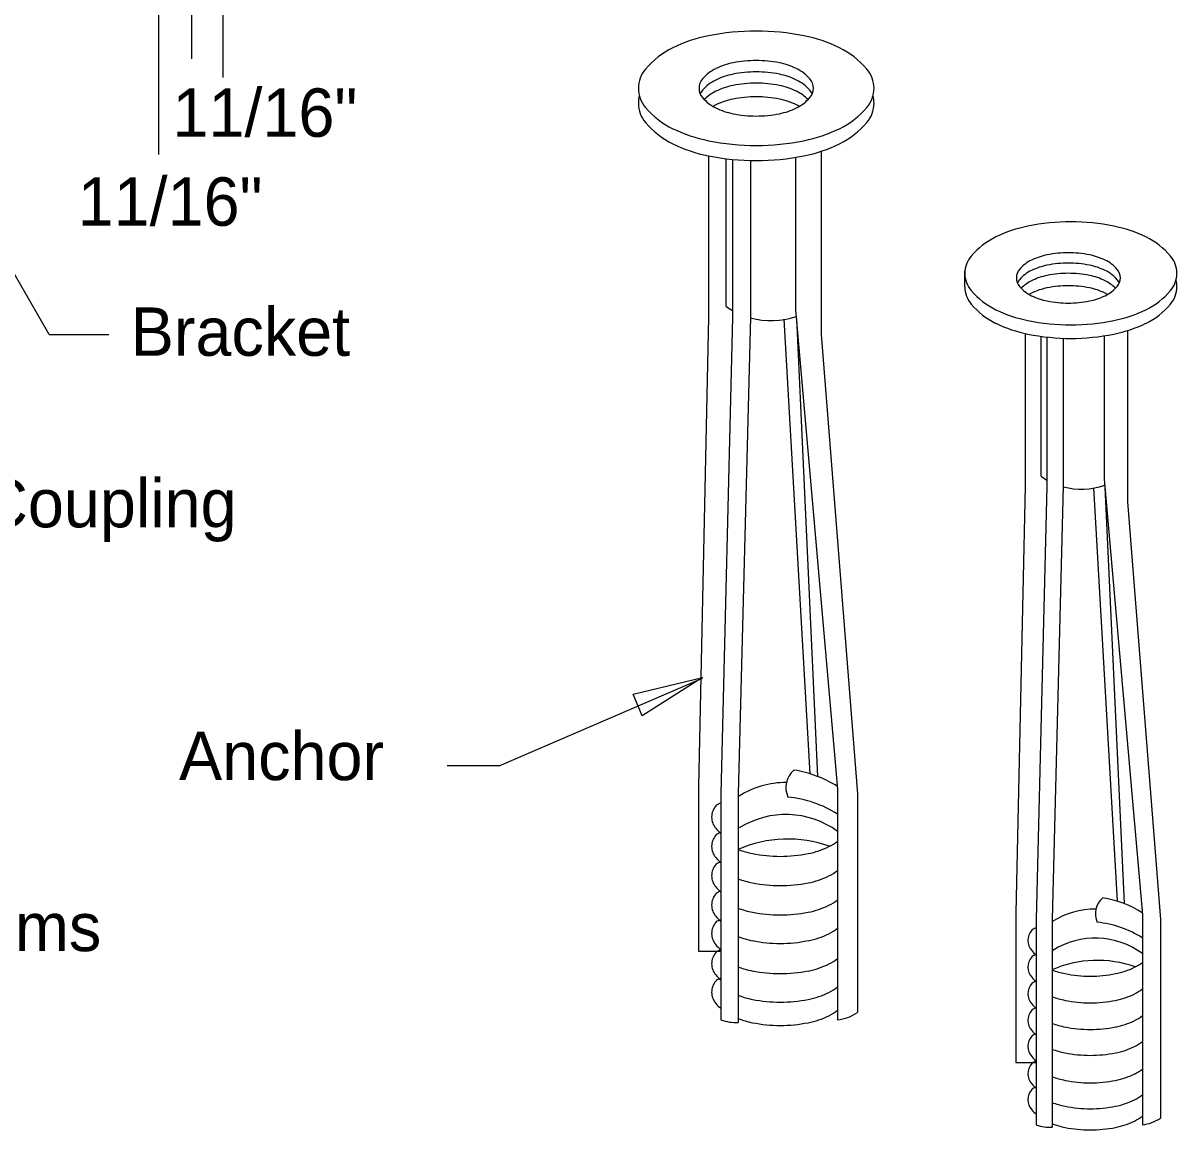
# Model space of a CAD drawing. Extents: x 12.3 to 19.6, y 5.9 to 16.2.
# Drawn here: x 17.486 to 18.916, y 8.1 to 9.472 of the extents above; entities that cross this region are included whole.
import ezdxf

# ---------------------------------------------------------------- set-up
doc = ezdxf.new("R2010")
doc.units = 0
for name, color, linetype in [('DETL-DIMS', 7, 'Continuous'), ('DETL-LINE', 7, 'Continuous'), ('DETL-NOTE', 7, 'Continuous')]:
    doc.layers.add(name, color=color, linetype=linetype)

msp = doc.modelspace()

# ---------------------------------------------------------------- linework, layer by layer
at = {"layer": 'DETL-DIMS'}
for p, q in [((17.6945, 10.224), (17.6945, 9.4278)), ((17.6539, 9.5709), (17.6539, 9.3091)), ((17.7336, 9.5458), (17.7336, 9.4046)), ((17.5181, 9.086), (17.3812, 9.3241)), ((17.5181, 9.086), (17.5922, 9.086)), ((18.076, 8.551), (18.3282, 8.6596)), ((18.076, 8.551), (18.0115, 8.551))]:
    msp.add_line(p, q, dxfattribs=at)
at = {"layer": 'DETL-LINE'}
for p, q in [((18.4753, 9.3132), (18.4753, 9.0858)), ((18.3356, 9.3075), (18.3356, 9.1074)), ((18.3576, 9.1207), (18.3576, 9.304)), ((18.3656, 9.3031), (18.3656, 9.1074)), ((18.3878, 9.3017), (18.3878, 9.1074)), ((18.4437, 9.3057), (18.4437, 9.1166)), ((18.6535, 9.145), (18.6536, 9.1644)), ((18.4437, 9.1166), (18.4957, 8.5223)), ((18.3356, 9.1074), (18.3232, 8.5254)), ((18.3656, 9.1074), (18.3509, 8.5162)), ((18.3878, 9.1074), (18.3725, 8.5162)), ((18.4292, 9.1051), (18.4612, 8.5412)), ((18.4446, 9.1058), (18.4708, 8.5379)), ((18.4753, 9.0858), (18.5204, 8.5162)), ((18.7281, 9.0872), (18.7281, 8.898)), ((18.8263, 9.0843), (18.8263, 8.9064)), ((18.8551, 9.0908), (18.8551, 8.8784)), ((18.748, 8.9101), (18.748, 9.0837)), ((18.7553, 9.0828), (18.7553, 8.898)), ((18.7755, 9.0813), (18.7755, 8.898)), ((18.8263, 8.9064), (18.8736, 8.3661)), ((18.7281, 8.898), (18.7167, 8.3689)), ((18.7553, 8.898), (18.742, 8.3605)), ((18.7755, 8.898), (18.7616, 8.3605)), ((18.8131, 8.8959), (18.8422, 8.3832)), ((18.8271, 8.8965), (18.8509, 8.3803)), ((18.8551, 8.8784), (18.896, 8.3605)), ((18.3232, 8.5254), (18.3232, 8.321)), ((18.3509, 8.5162), (18.3509, 8.236)), ((18.3725, 8.5162), (18.3725, 8.2329)), ((18.4957, 8.5223), (18.4957, 8.236)), ((18.5204, 8.5162), (18.5204, 8.2452)), ((18.7167, 8.3689), (18.7167, 8.1831)), ((18.742, 8.3605), (18.742, 8.1058)), ((18.7616, 8.3605), (18.7616, 8.103)), ((18.8736, 8.3661), (18.8736, 8.1058)), ((18.896, 8.3605), (18.896, 8.1142)), ((18.3232, 8.321), (18.3509, 8.321)), ((18.7167, 8.1831), (18.742, 8.1831))]:
    msp.add_line(p, q, dxfattribs=at)
msp.add_lwpolyline([(18.2535, 8.6132), (18.2421, 8.64), (18.3282, 8.6606)], close=True, dxfattribs=at)
for centre, radius, start, end in [((18.3719, 9.2758), 0.1842, 101.3709, 115.8973), ((18.3948, 9.1622), 0.3, 90, 101.3709), ((18.3948, 9.1622), 0.3, 78.6291, 90), ((18.4176, 9.2758), 0.1842, 64.1027, 78.6291), ((18.3373, 9.3471), 0.1049, 115.8973, 139.5312), ((18.4522, 9.3471), 0.1049, 40.4688, 64.1027), ((18.2855, 9.3913), 0.0368, 139.5312, 180), ((18.3669, 9.3698), 0.0509, 115.8664, 139.4922), ((18.3837, 9.3351), 0.0895, 101.3557, 115.8664), ((18.3948, 9.2799), 0.1458, 90, 101.3557), ((18.3948, 9.2799), 0.1458, 78.6443, 90), ((18.4059, 9.3351), 0.0895, 64.1336, 78.6443), ((18.4227, 9.3698), 0.0509, 40.5078, 64.1336), ((18.5041, 9.3913), 0.0368, 0, 40.4688), ((18.3417, 9.3913), 0.0178, 139.4922, 180), ((18.3669, 9.3557), 0.0509, 115.8664, 139.4922), ((18.3837, 9.321), 0.0895, 101.3557, 115.8664), ((18.3948, 9.2658), 0.1458, 90, 101.3557), ((18.3948, 9.2658), 0.1458, 78.6443, 90), ((18.4059, 9.321), 0.0895, 64.1336, 78.6443), ((18.4227, 9.3557), 0.0509, 40.5078, 64.1336), ((18.4479, 9.3913), 0.0178, 360, 40.5078), ((18.2855, 9.3913), 0.0368, 180, 220.4688), ((18.3417, 9.3913), 0.0178, 180, 220.5078), ((18.3417, 9.3772), 0.0178, 139.4922, 156.7461), ((18.3669, 9.3417), 0.0509, 115.8664, 135.6907), ((18.3837, 9.307), 0.0895, 101.3557, 115.8664), ((18.3948, 9.2518), 0.1458, 90, 101.3557), ((18.3948, 9.2518), 0.1458, 78.6443, 90), ((18.4059, 9.307), 0.0895, 64.1336, 78.6443), ((18.4227, 9.3417), 0.0509, 44.3093, 64.1336), ((18.4479, 9.3913), 0.0178, 319.4922, 360), ((18.4479, 9.3772), 0.0178, 23.2539, 40.5078), ((18.5041, 9.3913), 0.0368, 319.5312, 360), ((18.2855, 9.3726), 0.0368, 165.2366, 180), ((18.2855, 9.3726), 0.0368, 180, 220.4688), ((18.3669, 9.4128), 0.0509, 220.5078, 244.1336), ((18.3669, 9.3248), 0.0509, 115.8664, 120.2074), ((18.3837, 9.2901), 0.0895, 101.3557, 115.8664), ((18.3948, 9.2349), 0.1458, 90, 101.3557), ((18.3948, 9.2349), 0.1458, 78.6443, 90), ((18.4059, 9.2901), 0.0895, 64.1336, 78.6443), ((18.4227, 9.4128), 0.0509, 295.8664, 319.4922), ((18.4227, 9.3248), 0.0509, 59.7926, 64.1336), ((18.5041, 9.3726), 0.0368, 319.5312, 360), ((18.5041, 9.3726), 0.0368, 0, 14.7634), ((18.3373, 9.4355), 0.1049, 220.4688, 244.1027), ((18.3837, 9.4475), 0.0895, 244.1336, 258.6443), ((18.3948, 9.5027), 0.1458, 258.6443, 270), ((18.3948, 9.5027), 0.1458, 270, 281.3557), ((18.4059, 9.4475), 0.0895, 281.3557, 295.8664), ((18.4522, 9.4355), 0.1049, 295.8973, 319.5312), ((18.3373, 9.4168), 0.1049, 220.4688, 244.1027), ((18.4522, 9.4168), 0.1049, 295.8973, 319.5312), ((18.3719, 9.5069), 0.1842, 244.1027, 258.6291), ((18.4176, 9.5069), 0.1842, 281.3709, 295.8973), ((18.3719, 9.4881), 0.1842, 244.1027, 258.6291), ((18.3948, 9.6204), 0.3, 258.6291, 270), ((18.3948, 9.6204), 0.3, 270, 281.3709), ((18.4176, 9.4881), 0.1842, 281.3709, 295.8973), ((18.3948, 9.6016), 0.3, 258.6291, 270), ((18.3948, 9.6016), 0.3, 270, 281.3709), ((18.7644, 9.0578), 0.1658, 101.3709, 115.8973), ((18.785, 8.9557), 0.27, 90, 101.3709), ((18.785, 8.9557), 0.27, 78.6291, 90), ((18.8055, 9.0578), 0.1658, 64.1027, 78.6291), ((18.7333, 9.122), 0.0944, 115.8973, 139.5312), ((18.8367, 9.122), 0.0944, 40.4688, 64.1027), ((18.7717, 9.105), 0.0813, 101.3557, 115.8664), ((18.7818, 9.0548), 0.1325, 90, 101.3557), ((18.7818, 9.0548), 0.1325, 78.6443, 90), ((18.7919, 9.105), 0.0813, 64.1336, 78.6443), ((18.6866, 9.1618), 0.0331, 139.5312, 180), ((18.7564, 9.1366), 0.0463, 115.8664, 139.4922), ((18.7717, 9.0922), 0.0813, 101.3557, 115.8664), ((18.7818, 9.042), 0.1325, 90, 101.3557), ((18.7818, 9.042), 0.1325, 78.6443, 90), ((18.7919, 9.0922), 0.0813, 64.1336, 78.6443), ((18.8072, 9.1366), 0.0463, 40.5078, 64.1336), ((18.8833, 9.1618), 0.0331, 360, 40.4688), ((18.6866, 9.1618), 0.0331, 180, 220.4688), ((18.7336, 9.1561), 0.0162, 139.4922, 180), ((18.7336, 9.1561), 0.0162, 180, 220.5078), ((18.7564, 9.1238), 0.0463, 115.8664, 139.4922), ((18.7717, 9.0795), 0.0813, 101.3557, 115.8664), ((18.7818, 9.0293), 0.1325, 90, 101.3557), ((18.7818, 9.0293), 0.1325, 78.6443, 90), ((18.7919, 9.0795), 0.0813, 64.1336, 78.6443), ((18.8072, 9.1238), 0.0463, 40.5078, 64.1336), ((18.8301, 9.1561), 0.0162, 360, 40.5078), ((18.8301, 9.1561), 0.0162, 319.4922, 0), ((18.8833, 9.1618), 0.0331, 319.5312, 360), ((18.6866, 9.145), 0.0331, 180, 220.4688), ((18.7336, 9.1433), 0.0162, 139.4922, 156.7461), ((18.7564, 9.1756), 0.0463, 220.5078, 244.1336), ((18.7564, 9.111), 0.0463, 115.8664, 135.6907), ((18.7717, 9.0641), 0.0813, 101.3557, 115.8664), ((18.7818, 9.0139), 0.1325, 90, 101.3557), ((18.7818, 9.0139), 0.1325, 78.6443, 90), ((18.7919, 9.0641), 0.0813, 64.1336, 78.6443), ((18.8072, 9.111), 0.0463, 44.3093, 64.1336), ((18.8072, 9.1756), 0.0463, 295.8664, 319.4922), ((18.8301, 9.1433), 0.0162, 23.2539, 40.5078), ((18.8833, 9.145), 0.0331, 319.5312, 0), ((18.8833, 9.145), 0.0331, 360, 14.7634), ((18.7333, 9.2016), 0.0944, 220.4688, 244.1027), ((18.7564, 9.0957), 0.0463, 115.8664, 120.2074), ((18.7717, 9.2072), 0.0813, 244.1336, 258.6443), ((18.7818, 9.2574), 0.1325, 258.6443, 270), ((18.7818, 9.2574), 0.1325, 270, 281.3557), ((18.7919, 9.2072), 0.0813, 281.3557, 295.8664), ((18.8072, 9.0957), 0.0463, 59.7926, 64.1336), ((18.8367, 9.2016), 0.0944, 295.8973, 319.5312), ((18.4128, 9.1985), 0.0954, 234.6116, 240.3143), ((18.7333, 9.1847), 0.0944, 220.4688, 244.1027), ((18.7644, 9.2658), 0.1658, 244.1027, 258.6291), ((18.8055, 9.2658), 0.1658, 281.3709, 295.8973), ((18.8367, 9.1847), 0.0944, 295.8973, 319.5312), ((18.4128, 9.1985), 0.0954, 254.7883, 289.3036), ((18.7644, 9.249), 0.1658, 244.1027, 258.6291), ((18.785, 9.368), 0.27, 258.6291, 270), ((18.785, 9.368), 0.27, 270, 281.3709), ((18.8055, 9.249), 0.1658, 281.3709, 295.8973), ((18.785, 9.3511), 0.27, 258.6291, 270), ((18.785, 9.3511), 0.27, 270, 281.3709), ((18.7982, 8.9808), 0.0867, 234.6116, 240.3143), ((18.7982, 8.9808), 0.0867, 254.7883, 289.3036), ((18.4597, 8.5241), 0.0281, 129.9978, 204.8964), ((18.4203, 8.4062), 0.1411, 57.6772, 81.3099), ((18.4316, 8.4219), 0.1084, 89.658, 122.2181), ((18.4203, 8.3719), 0.1411, 57.6772, 84.3464), ((18.361, 8.4875), 0.0214, 139.4922, 180), ((18.3912, 8.4617), 0.0611, 138.7828, 139.4922), ((18.3607, 8.4769), 0.0295, 109.4731, 121.692), ((18.361, 8.4875), 0.0214, 180, 220.5078), ((18.4316, 8.3823), 0.1084, 53.7599, 122.2181), ((18.3912, 8.5133), 0.0611, 220.5078, 228.7285), ((18.361, 8.4511), 0.0214, 139.4922, 180), ((18.3912, 8.4253), 0.0611, 138.7828, 139.4922), ((18.3607, 8.4405), 0.0295, 109.4731, 121.692), ((18.4341, 8.307), 0.1533, 70.2819, 113.692), ((18.4582, 8.5058), 0.0611, 295.8664, 307.9171), ((18.361, 8.4511), 0.0214, 180, 220.5078), ((18.4114, 8.5475), 0.1074, 248.7495, 258.6443), ((18.4247, 8.6137), 0.1749, 258.6443, 270), ((18.4247, 8.6137), 0.1749, 270, 281.3557), ((18.438, 8.5475), 0.1074, 281.3557, 295.8664), ((18.361, 8.4148), 0.0214, 139.4922, 180), ((18.3912, 8.4769), 0.0611, 220.5078, 228.7285), ((18.3912, 8.389), 0.0611, 138.7828, 139.4922), ((18.3607, 8.4041), 0.0295, 109.4731, 121.692), ((18.361, 8.4148), 0.0214, 180, 220.5078), ((18.438, 8.5111), 0.1074, 281.3557, 295.8664), ((18.4582, 8.4695), 0.0611, 295.8664, 307.9171), ((18.3912, 8.4406), 0.0611, 220.5078, 228.7285), ((18.4114, 8.5111), 0.1074, 248.7495, 258.6443), ((18.4247, 8.5774), 0.1749, 258.6443, 270), ((18.4247, 8.5774), 0.1749, 270, 281.3557), ((18.361, 8.3784), 0.0214, 139.4922, 180), ((18.3912, 8.3526), 0.0611, 138.7828, 139.4922), ((18.3607, 8.3678), 0.0295, 109.4731, 121.692), ((18.4582, 8.4331), 0.0611, 295.8664, 307.9171), ((18.8408, 8.3677), 0.0255, 129.9978, 204.8964), ((18.805, 8.2605), 0.1282, 57.6772, 81.3099), ((18.361, 8.3784), 0.0214, 180, 220.5078), ((18.4114, 8.4747), 0.1074, 248.7495, 258.6443), ((18.4247, 8.541), 0.1749, 258.6443, 270), ((18.4247, 8.541), 0.1749, 270, 281.3557), ((18.438, 8.4747), 0.1074, 281.3557, 295.8664), ((18.8153, 8.2748), 0.0986, 89.658, 122.2181), ((18.361, 8.3431), 0.0214, 139.4922, 180), ((18.3912, 8.4042), 0.0611, 220.5078, 228.7285), ((18.3912, 8.3173), 0.0611, 138.7828, 139.4922), ((18.3607, 8.3324), 0.0295, 109.4731, 121.692), ((18.805, 8.2294), 0.1282, 57.6772, 84.3464), ((18.361, 8.3431), 0.0214, 180, 220.5078), ((18.438, 8.4394), 0.1074, 281.3557, 295.8664), ((18.4582, 8.3978), 0.0611, 295.8664, 307.9171), ((18.7511, 8.3345), 0.0194, 139.4922, 180), ((18.7786, 8.311), 0.0555, 138.7828, 139.4922), ((18.7509, 8.3248), 0.0268, 109.4731, 121.692), ((18.3912, 8.3689), 0.0611, 220.5078, 228.7285), ((18.4114, 8.4394), 0.1074, 248.7495, 258.6443), ((18.4247, 8.5057), 0.1749, 258.6443, 270), ((18.4247, 8.5057), 0.1749, 270, 281.3557), ((18.7511, 8.3345), 0.0194, 180, 220.5078), ((18.8153, 8.2388), 0.0986, 53.7599, 122.2181), ((18.361, 8.3056), 0.0214, 139.4922, 180), ((18.3912, 8.2798), 0.0611, 138.7828, 139.4922), ((18.3607, 8.295), 0.0295, 109.4731, 121.692), ((18.4582, 8.3603), 0.0611, 295.8664, 307.9171), ((18.7511, 8.3014), 0.0194, 139.4922, 180), ((18.7786, 8.3579), 0.0555, 220.5078, 228.7285), ((18.7786, 8.278), 0.0555, 138.7828, 139.4922), ((18.7509, 8.2918), 0.0268, 109.4731, 121.692), ((18.361, 8.3056), 0.0214, 180, 220.5078), ((18.4114, 8.4019), 0.1074, 248.7495, 258.6443), ((18.438, 8.4019), 0.1074, 281.3557, 295.8664), ((18.7511, 8.3014), 0.0194, 180, 220.5078), ((18.8176, 8.1704), 0.1394, 70.2819, 113.692), ((18.7969, 8.389), 0.0976, 248.7495, 258.6443), ((18.8211, 8.389), 0.0976, 281.3557, 295.8664), ((18.8395, 8.3511), 0.0555, 295.8664, 307.9171), ((18.361, 8.2703), 0.0214, 139.4922, 180), ((18.3912, 8.3314), 0.0611, 220.5078, 228.7285), ((18.3912, 8.2445), 0.0611, 138.7828, 139.4922), ((18.3607, 8.2597), 0.0295, 109.4731, 121.692), ((18.4247, 8.4682), 0.1749, 258.6443, 270), ((18.4247, 8.4682), 0.1749, 270, 281.3557), ((18.7786, 8.3249), 0.0555, 220.5078, 228.7285), ((18.7509, 8.2587), 0.0268, 109.4731, 121.692), ((18.809, 8.4492), 0.159, 258.6443, 270), ((18.809, 8.4492), 0.159, 270, 281.3557), ((18.361, 8.2703), 0.0214, 180, 220.5078), ((18.438, 8.3666), 0.1074, 281.3557, 295.8664), ((18.4582, 8.325), 0.0611, 295.8664, 307.9171), ((18.7511, 8.2683), 0.0194, 139.4922, 180), ((18.7786, 8.2449), 0.0555, 138.7828, 139.4922), ((18.8395, 8.3181), 0.0555, 295.8664, 307.9171), ((18.3912, 8.2961), 0.0611, 220.5078, 228.7285), ((18.4114, 8.3666), 0.1074, 248.7495, 258.6443), ((18.4247, 8.4329), 0.1749, 258.6443, 270), ((18.4247, 8.4329), 0.1749, 270, 281.3557), ((18.7511, 8.2683), 0.0194, 180, 220.5078), ((18.7786, 8.2918), 0.0555, 220.5078, 228.7285), ((18.7969, 8.3559), 0.0976, 248.7495, 258.6443), ((18.809, 8.4161), 0.159, 258.6443, 270), ((18.809, 8.4161), 0.159, 270, 281.3557), ((18.8211, 8.3559), 0.0976, 281.3557, 295.8664), ((18.438, 8.3377), 0.1074, 281.3557, 295.8664), ((18.4582, 8.2961), 0.0611, 295.8664, 307.9171), ((18.4882, 8.2935), 0.0581, 277.441, 303.6474), ((18.7511, 8.2353), 0.0194, 139.4922, 180), ((18.7786, 8.2118), 0.0555, 138.7828, 139.4922), ((18.7509, 8.2256), 0.0268, 109.4731, 121.692), ((18.8395, 8.285), 0.0555, 295.8664, 307.9171), ((18.369, 8.2853), 0.0525, 249.9032, 273.8465), ((18.4114, 8.3377), 0.1074, 248.7495, 258.6443), ((18.4247, 8.404), 0.1749, 258.6443, 270), ((18.4247, 8.404), 0.1749, 270, 281.3557), ((18.7511, 8.2353), 0.0194, 180, 220.5078), ((18.7969, 8.3228), 0.0976, 248.7495, 258.6443), ((18.809, 8.3831), 0.159, 258.6443, 270), ((18.809, 8.3831), 0.159, 270, 281.3557), ((18.8211, 8.3228), 0.0976, 281.3557, 295.8664), ((18.7511, 8.2032), 0.0194, 139.4922, 180), ((18.7786, 8.2587), 0.0555, 220.5078, 228.7285), ((18.7786, 8.1797), 0.0555, 138.7828, 139.4922), ((18.7509, 8.1935), 0.0268, 109.4731, 121.692), ((18.7511, 8.2032), 0.0194, 180, 220.5078), ((18.7969, 8.2907), 0.0976, 248.7495, 258.6443), ((18.8211, 8.2907), 0.0976, 281.3557, 295.8664), ((18.8395, 8.2529), 0.0555, 295.8664, 307.9171), ((18.7786, 8.2266), 0.0555, 220.5078, 228.7285), ((18.7509, 8.1595), 0.0268, 109.4731, 121.692), ((18.809, 8.351), 0.159, 258.6443, 270), ((18.809, 8.351), 0.159, 270, 281.3557), ((18.7511, 8.1691), 0.0194, 139.4922, 180), ((18.7511, 8.1691), 0.0194, 180, 220.5078), ((18.7786, 8.1457), 0.0555, 138.7828, 139.4922), ((18.8211, 8.2567), 0.0976, 281.3557, 295.8664), ((18.8395, 8.2188), 0.0555, 295.8664, 307.9171), ((18.7786, 8.1926), 0.0555, 220.5078, 228.7285), ((18.7969, 8.2567), 0.0976, 248.7495, 258.6443), ((18.809, 8.3169), 0.159, 258.6443, 270), ((18.809, 8.3169), 0.159, 270, 281.3557), ((18.7511, 8.137), 0.0194, 139.4922, 180), ((18.7786, 8.1135), 0.0555, 138.7828, 139.4922), ((18.7509, 8.1274), 0.0268, 109.4731, 121.692), ((18.8395, 8.1867), 0.0555, 295.8664, 307.9171), ((18.7511, 8.137), 0.0194, 180, 220.5078), ((18.7969, 8.2246), 0.0976, 248.7495, 258.6443), ((18.809, 8.2848), 0.159, 258.6443, 270), ((18.809, 8.2848), 0.159, 270, 281.3557), ((18.8211, 8.2246), 0.0976, 281.3557, 295.8664), ((18.7786, 8.1605), 0.0555, 220.5078, 228.7285), ((18.8395, 8.1605), 0.0555, 295.8664, 307.9171), ((18.8668, 8.1581), 0.0528, 277.441, 303.6474), ((18.7584, 8.1506), 0.0477, 249.9032, 273.8465), ((18.7969, 8.1983), 0.0976, 248.7495, 258.6443), ((18.809, 8.2585), 0.159, 258.6443, 270), ((18.809, 8.2585), 0.159, 270, 281.3557), ((18.8211, 8.1983), 0.0976, 281.3557, 295.8664)]:
    msp.add_arc(centre, radius, start, end, dxfattribs=at)

# ---------------------------------------------------------------- texts
at = {"layer": 'DETL-NOTE'}
for s, p in [('11/16"', (17.6711, 9.3311)), ('11/16"', (17.5535, 9.2208)), ('Bracket', (17.6194, 9.0595)), ('Coupling', (17.4339, 8.8468)), ('Anchor', (17.6792, 8.5333)), ('Shims', (17.3599, 8.3212))]:
    msp.add_text(s, height=0.06, dxfattribs=at).set_placement(p)

doc.saveas('drawing.dxf')
